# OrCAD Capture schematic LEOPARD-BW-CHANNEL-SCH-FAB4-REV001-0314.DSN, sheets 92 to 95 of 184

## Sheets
92 083_WBG - DMI & USB: size A3; title: WBG - DMI & USB
93 081_MID-PLANE CONNECTOR: size A3; title: MID-PLANE CONNECTOR
94 080_PCIE RISER: size A2; title: PCIE RISER
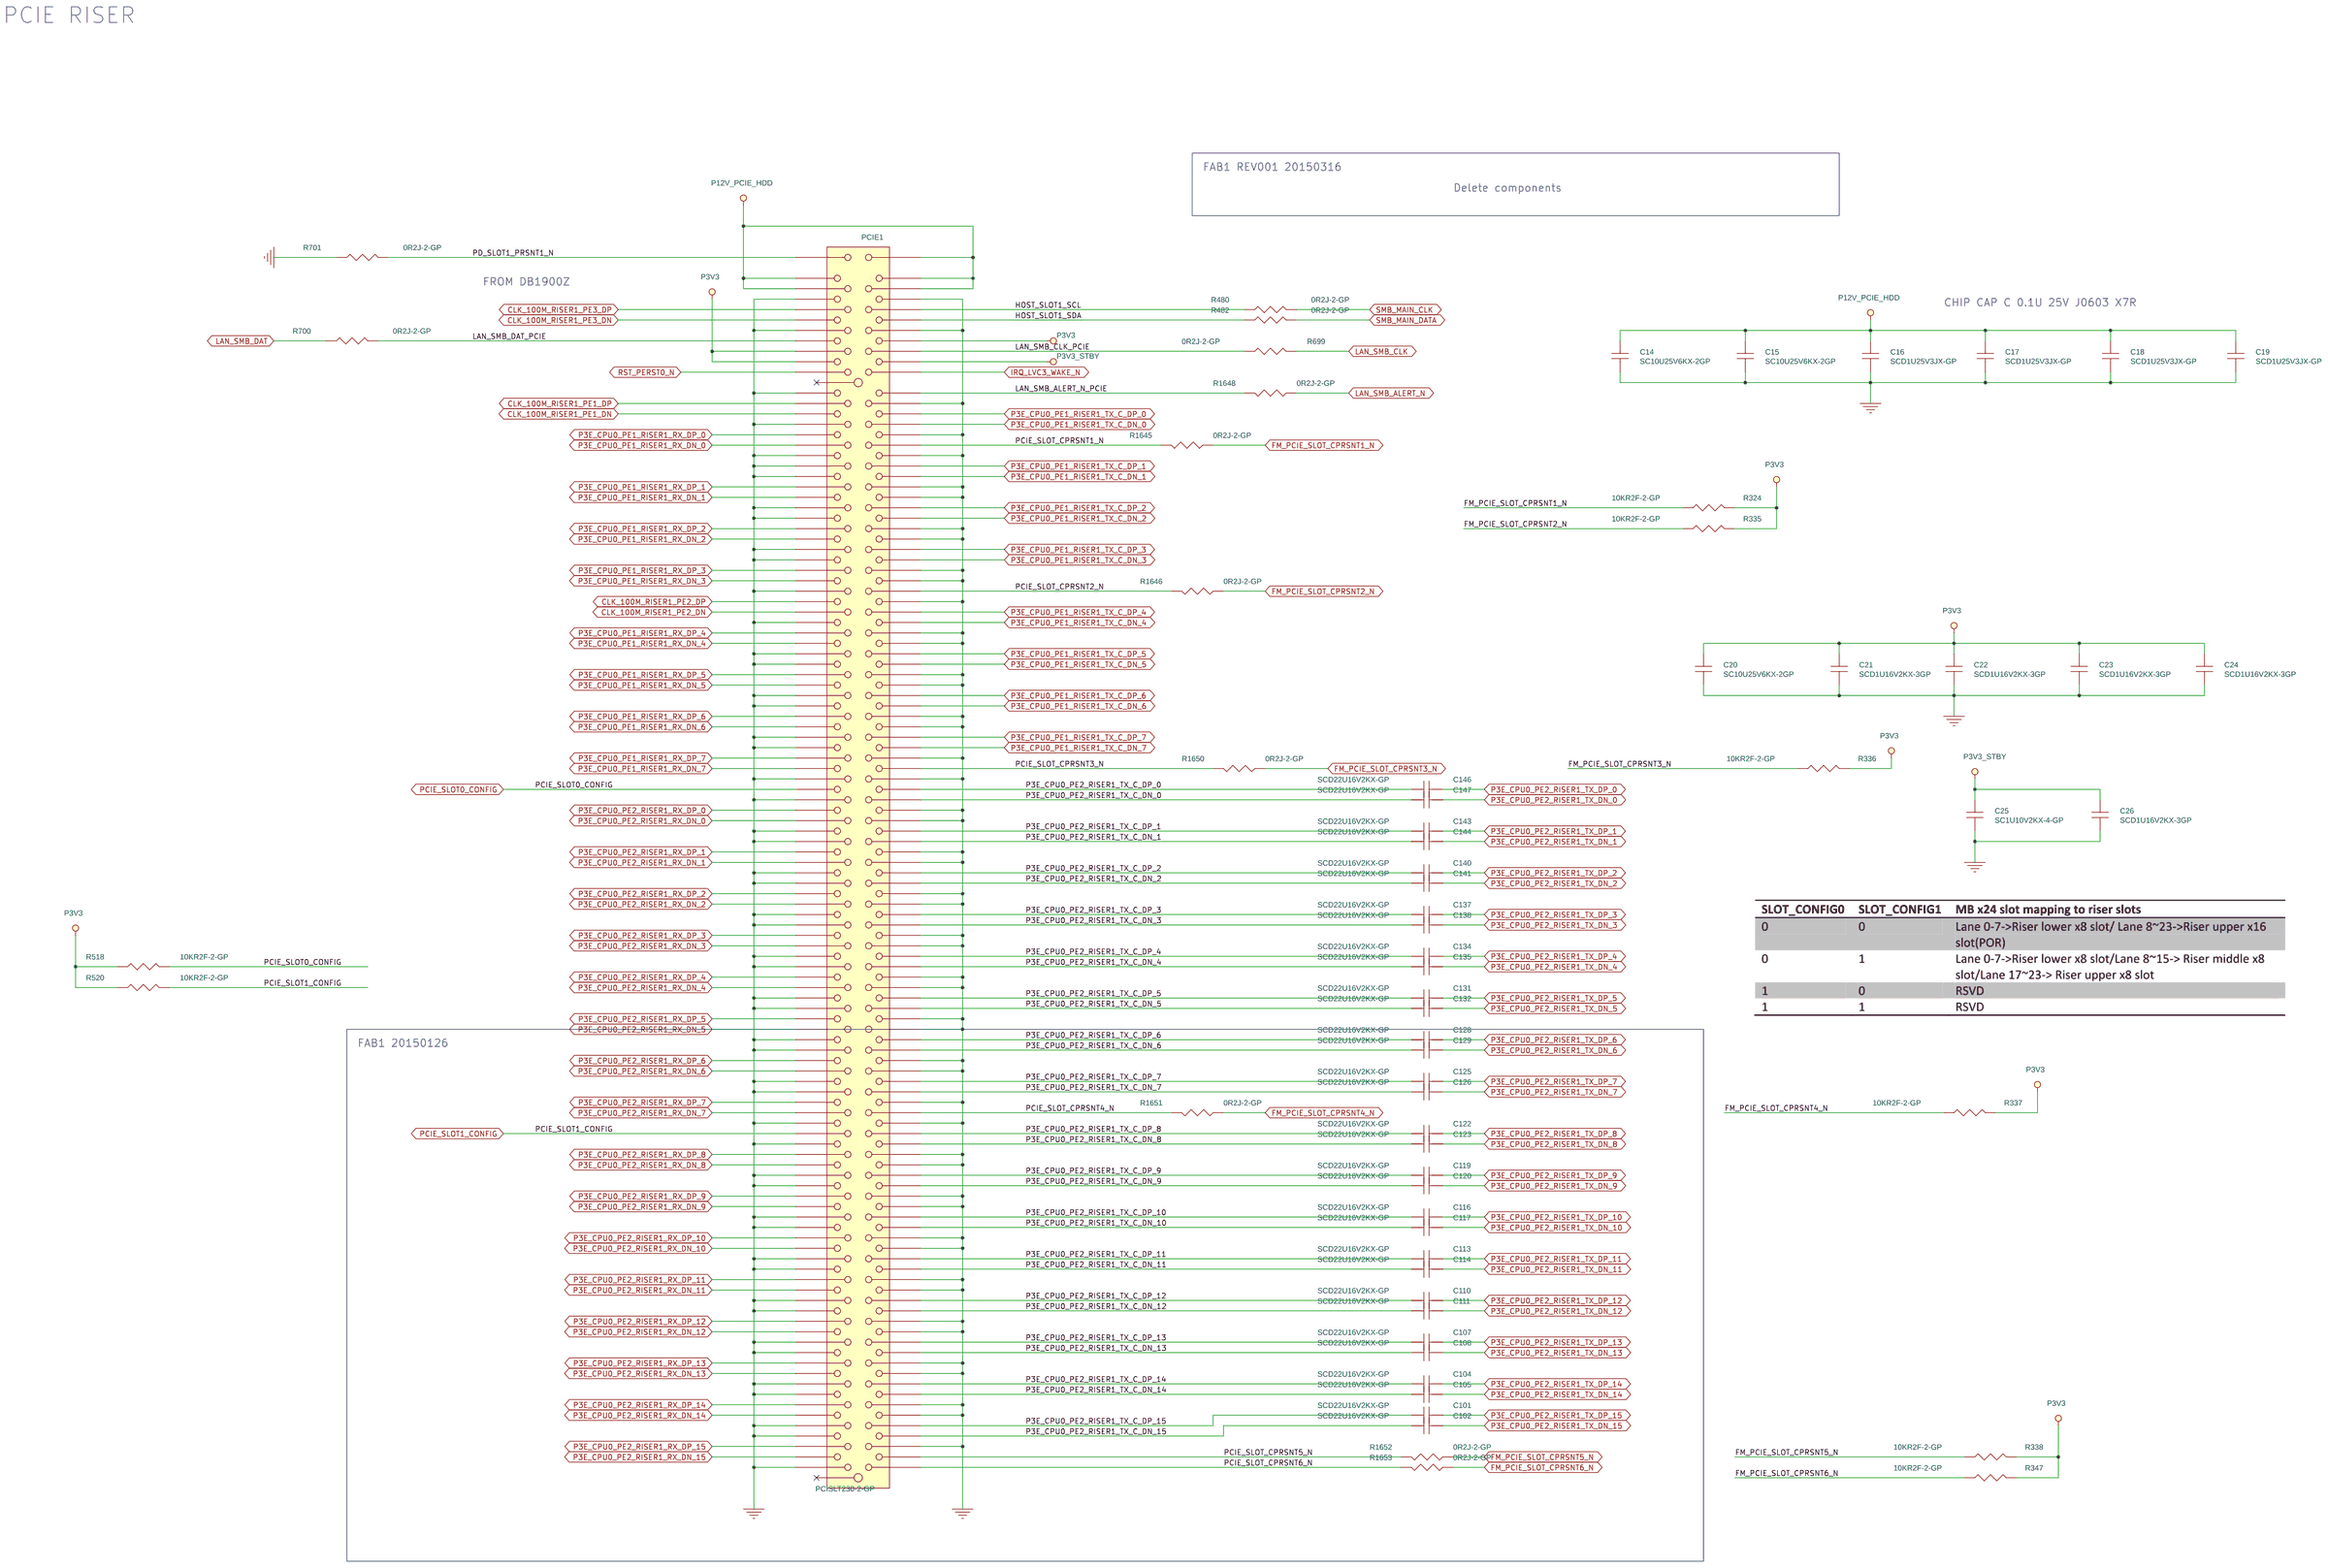
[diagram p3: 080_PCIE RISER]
95 079_MEZZ CONNECTOR: size A3; title: MEZZ CONNECTOR
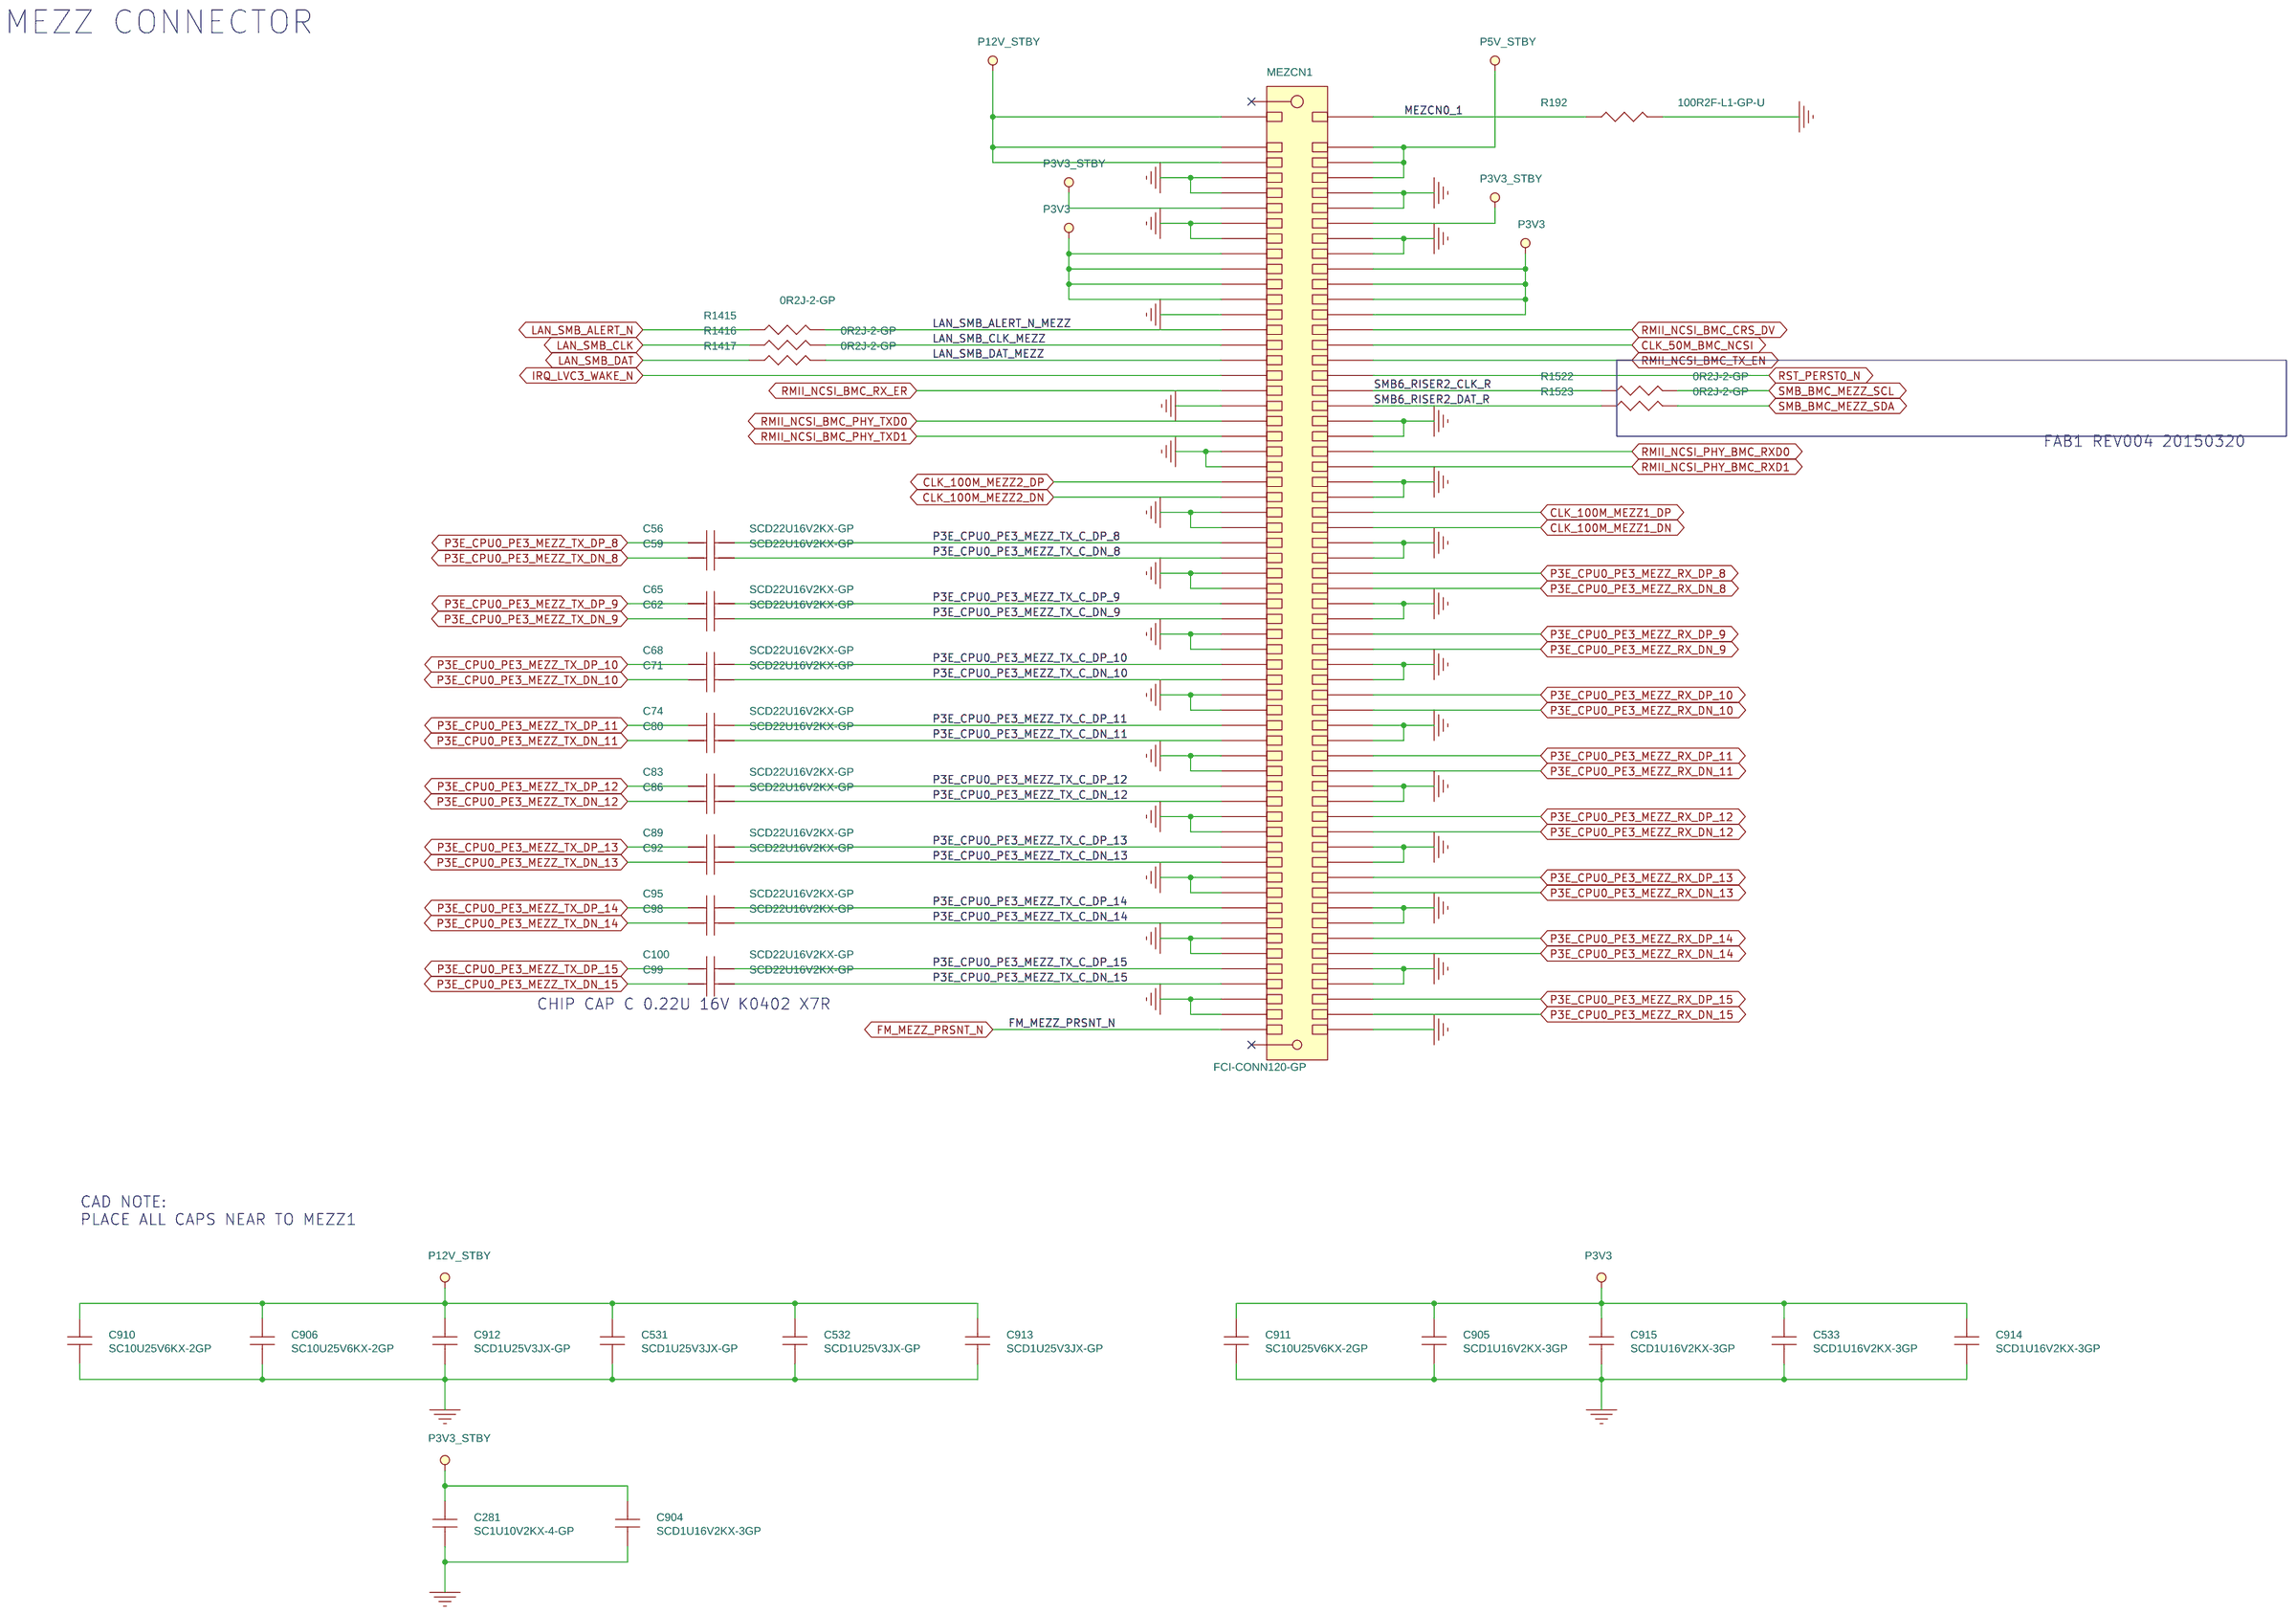
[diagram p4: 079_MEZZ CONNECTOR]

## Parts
sheet 079_MEZZ CONNECTOR
C56  SCD22U16V2KX-GP  [C402H22]
C59  SCD22U16V2KX-GP  [C402H22]
C62  SCD22U16V2KX-GP  [C402H22]
C65  SCD22U16V2KX-GP  [C402H22]
C68  SCD22U16V2KX-GP  [C402H22]
C71  SCD22U16V2KX-GP  [C402H22]
C74  SCD22U16V2KX-GP  [C402H22]
C80  SCD22U16V2KX-GP  [C402H22]
C83  SCD22U16V2KX-GP  [C402H22]
C86  SCD22U16V2KX-GP  [C402H22]
C89  SCD22U16V2KX-GP  [C402H22]
C92  SCD22U16V2KX-GP  [C402H22]
C95  SCD22U16V2KX-GP  [C402H22]
C98  SCD22U16V2KX-GP  [C402H22]
C99  SCD22U16V2KX-GP  [C402H22]
C100  SCD22U16V2KX-GP  [C402H22]
C281  SC1U10V2KX-4-GP  [C402H22]
C531  SCD1U25V3JX-GP  [C603H36]
C532  SCD1U25V3JX-GP  [C603H36]
C533  SCD1U16V2KX-3GP  [C402H22]
C904  SCD1U16V2KX-3GP  [C402H22]
C905  SCD1U16V2KX-3GP  [C402H22]
C906  SC10U25V6KX-2GP  [C1206H63]
C910  SC10U25V6KX-2GP  [C1206H63]
C911  SC10U25V6KX-2GP  [C1206H63]
C912  SCD1U25V3JX-GP  [C603H36]
C913  SCD1U25V3JX-GP  [C603H36]
C914  SCD1U16V2KX-3GP  [C402H22]
C915  SCD1U16V2KX-3GP  [C402H22]
MEZCN1  FCI-CONN120-GP  [61082-121402LF-U]
R192  100R2F-L1-GP-U  [R402H14]
R1415  0R2J-2-GP  [R402H16]
R1416  0R2J-2-GP  [R402H16]
R1417  0R2J-2-GP  [R402H16]
R1522  0R2J-2-GP  [R402H16]
R1523  0R2J-2-GP  [R402H16]
sheet 080_PCIE RISER
C14  SC10U25V6KX-2GP  [C1206H63]
C15  SC10U25V6KX-2GP  [C1206H63]
C16  SCD1U25V3JX-GP  [C603H36]
C17  SCD1U25V3JX-GP  [C603H36]
C18  SCD1U25V3JX-GP  [C603H36]
C19  SCD1U25V3JX-GP  [C603H36]
C20  SC10U25V6KX-2GP  [C1206H63]
C21  SCD1U16V2KX-3GP  [C402H22]
C22  SCD1U16V2KX-3GP  [C402H22]
C23  SCD1U16V2KX-3GP  [C402H22]
C24  SCD1U16V2KX-3GP  [C402H22]
C25  SC1U10V2KX-4-GP  [C402H22]
C26  SCD1U16V2KX-3GP  [C402H22]
C101  SCD22U16V2KX-GP  [C402H22]
C102  SCD22U16V2KX-GP  [C402H22]
C104  SCD22U16V2KX-GP  [C402H22]
C105  SCD22U16V2KX-GP  [C402H22]
C107  SCD22U16V2KX-GP  [C402H22]
C108  SCD22U16V2KX-GP  [C402H22]
C110  SCD22U16V2KX-GP  [C402H22]
C111  SCD22U16V2KX-GP  [C402H22]
C113  SCD22U16V2KX-GP  [C402H22]
C114  SCD22U16V2KX-GP  [C402H22]
C116  SCD22U16V2KX-GP  [C402H22]
C117  SCD22U16V2KX-GP  [C402H22]
C119  SCD22U16V2KX-GP  [C402H22]
C120  SCD22U16V2KX-GP  [C402H22]
C122  SCD22U16V2KX-GP  [C402H22]
C123  SCD22U16V2KX-GP  [C402H22]
C125  SCD22U16V2KX-GP  [C402H22]
C126  SCD22U16V2KX-GP  [C402H22]
C128  SCD22U16V2KX-GP  [C402H22]
C129  SCD22U16V2KX-GP  [C402H22]
C131  SCD22U16V2KX-GP  [C402H22]
C132  SCD22U16V2KX-GP  [C402H22]
C134  SCD22U16V2KX-GP  [C402H22]
C135  SCD22U16V2KX-GP  [C402H22]
C137  SCD22U16V2KX-GP  [C402H22]
C138  SCD22U16V2KX-GP  [C402H22]
C140  SCD22U16V2KX-GP  [C402H22]
C141  SCD22U16V2KX-GP  [C402H22]
C143  SCD22U16V2KX-GP  [C402H22]
C144  SCD22U16V2KX-GP  [C402H22]
C146  SCD22U16V2KX-GP  [C402H22]
C147  SCD22U16V2KX-GP  [C402H22]
PCIE1  PCISLT230-2-GP  [10063960-10010TLF]
R324  10KR2F-2-GP  [R402H16]
R335  10KR2F-2-GP  [R402H16]
R336  10KR2F-2-GP  [R402H16]
R337  10KR2F-2-GP  [R402H16]
R338  10KR2F-2-GP  [R402H16]
R347  10KR2F-2-GP  [R402H16]
R480  0R2J-2-GP  [R402H16]
R482  0R2J-2-GP  [R402H16]
R518  10KR2F-2-GP  [R402H16]
R520  10KR2F-2-GP  [R402H16]
R699  0R2J-2-GP  [R402H16]
R700  0R2J-2-GP  [R402H16]
R701  0R2J-2-GP  [R402H16]
R1645  0R2J-2-GP  [R402H16]
R1646  0R2J-2-GP  [R402H16]
R1648  0R2J-2-GP  [R402H16]
R1650  0R2J-2-GP  [R402H16]
R1651  0R2J-2-GP  [R402H16]
R1652  0R2J-2-GP  [R402H16]
R1653  0R2J-2-GP  [R402H16]
sheet 081_MID-PLANE CONNECTOR
C33  SCD1U16V2KX-3GP  [C402H22]
C173  SCD22U16V2KX-GP  [C402H22]
C174  SCD22U16V2KX-GP  [C402H22]
C176  SCD22U16V2KX-GP  [C402H22]
C177  SCD22U16V2KX-GP  [C402H22]
C179  SCD22U16V2KX-GP  [C402H22]
C180  SCD22U16V2KX-GP  [C402H22]
C182  SCD22U16V2KX-GP  [C402H22]
C183  SCD22U16V2KX-GP  [C402H22]
C185  SCD22U16V2KX-GP  [C402H22]
C186  SCD22U16V2KX-GP  [C402H22]
C188  SCD22U16V2KX-GP  [C402H22]
C189  SCD22U16V2KX-GP  [C402H22]
C191  SCD22U16V2KX-GP  [C402H22]
C192  SCD22U16V2KX-GP  [C402H22]
C194  SCD22U16V2KX-GP  [C402H22]
C195  SCD22U16V2KX-GP  [C402H22]
D13  RB521SM-30T2R-GP  [D1608-035030AKH28]
D14  RB521SM-30T2R-GP  [D1608-035030AKH28]
MIDCN1  TE-CON8-S-GP  [2-1734598-8]
MIDCN2  DM-FCI-CONN76-8R-GP-U-01  [DM-FIT76P179295UH459-01]
Q9  MMBT3904-9-GP  [SOT23CBE2D4H44]
Q18  2N7002-7F-GP  [SOT23DGS2D4H44]
R181  10KR2F-2-GP  [R402H16]
R349  10KR2F-2-GP  [R402H16]
R382  100R2F-L1-GP-U  [R402H14]
R528  0R2J-2-GP  [R402H16]
R1053  0R2J-2-GP  [R402H16]
R1217  0R2J-2-GP  [R402H16]
R1219  0R2J-2-GP  [R402H16]
R1221  6K2R2F-GP  [R402H16]
R1222  15KR2F-GP  [R402H16]
R1267  0R2J-2-GP  [R402H16]
R1384  0R2J-2-GP  [R402H16]
R1880  10KR2J-3-GP  [R402H16]
sheet 083_WBG - DMI & USB
C204  SCD1U16V2KX-3GP  [C402H22]
C205  SCD1U16V2KX-3GP  [C402H22]
C280  SCD1U16V2KX-3GP  [C402H22]
C284  SCD1U16V2KX-3GP  [C402H22]
C285  SCD1U16V2KX-3GP  [C402H22]
C286  SCD1U16V2KX-3GP  [C402H22]
C287  SCD1U16V2KX-3GP  [C402H22]
C288  SCD1U16V2KX-3GP  [C402H22]
C289  SCD1U16V2KX-3GP  [C402H22]
C290  SCD1U16V2KX-3GP  [C402H22]
C291  SCD1U16V2KX-3GP  [C402H22]
C292  SCD1U16V2KX-3GP  [C402H22]
C691  SCD1U16V2KX-3GP  [C402H22]
C693  SCD1U16V2KX-3GP  [C402H22]
C696  SCD1U16V2KX-3GP  [C402H22]
C699  SCD1U16V2KX-3GP  [C402H22]
C702  SCD1U16V2KX-3GP  [C402H22]
C703  SCD1U16V2KX-3GP  [C402H22]
C704  SCD1U16V2KX-3GP  [C402H22]
C705  SCD1U16V2KX-3GP  [C402H22]
R217  10KR2F-2-GP  [R402H16]
R282  0R2J-2-GP  [R402H16]
R321  0R2J-2-GP  [R402H16]
R397  10KR2F-2-GP  [R402H16]
R401  10KR2F-2-GP  [R402H16]
R779  8K2R2J-3-GP  [R402H16]
R888  10KR2F-2-GP  [R402H16]
R889  10KR2F-2-GP  [R402H16]
WBG1  WELLSBURG-1-GP-U  [BGA836M25H87]  (sections A,B,C,D,E,F,G,H,I,J,K)

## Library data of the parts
C56 C59 C62 C65 C68 C71 C74 C80 C83 C86 C89 C92 C95 C98-C102 C104 C105 C107 C108 C110 C111 C113 C114 C116 C117 C119 C120 C122 C123 C125 C126 C128 C129 C131 C132 C134 C135 C137 C138 C140 C141 C143 C144 C146 C147 = SCD22U16V2KX-GP: CHIP CAP C 0.22U 16V K0402 X7R; GREENDFACTOR: R2_SA;HF_SA;G_SA;; Part Number: 78.22421.2FL; Part Type: SMD-BCG4; SPEC: http://wpqssvr.wistron.com.tw:7001/wpqs/servlet/COM.qpart.Attachment?PartNumber=78.22421.2FL
C25 C281 = SC1U10V2KX-4-GP: CHIP CAP C 1U 10V K 0402 X6S; GREENDFACTOR: R2_SA;HF_SA;; Part Number: 78.10523.8FL; Part Type: SMD-BCG6; SPEC: http://wpqssvr.wistron.com.tw:7001/wpqs/servlet/COM.qpart.Attachment?PartNumber=78.10523.8FL
C16-C19 C531 C532 C912 C913 = SCD1U25V3JX-GP: CHIP CAP C 0.1U 25V J0603 X7R; GREENDFACTOR: R2_SA;HF_SA;G_SA;; Part Number: 78.10432.2BL; Part Type: SMD-BCG2; SPEC: http://wpqssvr.wistron.com.tw:7001/wpqs/servlet/COM.qpart.Attachment?PartNumber=78.10432.2BL
C21-C24 C26 C533 C904 C905 C914 C915 = SCD1U16V2KX-3GP: CHIP CAP C 0.1U 16V K0402 X7R; CATEGORIES: CAP_1.xV; GREENDFACTOR: R2_SA;HF_SA;G_SA;; MAIN_SOURCE: M; Part Number: 78.10421.2FL; Part Type: SMD-BCG; SPEC: http://wpqssvr.wistron.com.tw:7001/wpqs/servlet/COM.qpart.Attachment?PartNumber=78.10421.2FL
C14 C15 C20 C906 C910 C911 = SC10U25V6KX-2GP: CHIP CAP C 10U 25V K1206 X6S; GREENDFACTOR: R2_SA;HF_SA;; Part Number: 78.10622.82L; Part Type: SMD-BCG; SPEC: http://wpqssvr.wistron.com.tw:7001/wpqs/servlet/COM.qpart.Attachment?PartNumber=78.10622.82L
MEZCN1 = FCI-CONN120-GP: CONN CTR SMD 120P 61082-121402LF; Category: MEZZ CONN; GREENDFACTOR: R2_C;; Part Number: 20.F1354.120; Part Type: CONN-G6; SPEC: http://wpqssvr.wistron.com.tw:7001/wpqs/servlet/COM.qpart.Attachment?PartNumber=20.F1354.120
R192 = 100R2F-L1-GP-U: CHIP RES 100 F 1/16W 0402; GREENDFACTOR: R2_SA;HF_SA;G_SA;; Part Number: 64.10005.6DL; Part Type: SMD-RG; SPEC: http://wpqssvr.wistron.com.tw:7001/wpqs/servlet/COM.qpart.Attachment?PartNumber=64.10005.6DL
R1415 = 0R2J-2-GP: CHIP RES 0 J 1/16W 0402; Belong: POP; Category: MEZZ CONN; Part Number: 63.R0034.1DL; Part Type: SMD-RG; Status: POP
R1416 R1417 R1522 R1523 = 0R2J-2-GP: CHIP RES 0 J 1/16W 0402; Belong: POP; Category: MEZZ CONN; GREENDFACTOR: R2_SA;HF_SA;G_SA;; Part Number: 63.R0034.1DL; Part Type: SMD-RG; SPEC: http://wpqssvr.wistron.com.tw:7001/wpqs/servlet/COM.qpart.Attachment?PartNumber=63.R0034.1DL
PCIE1 = PCISLT230-2-GP: CONN EDGE 230P ST 10063960-10010TLF; GREENDFACTOR: R2_SA;; Part Number: 20.50552.230; Part Type: CONN-G7; SPEC: http://wpqssvr.wistron.com.tw:7001/wpqs/servlet/COM.qpart.Attachment?PartNumber=20.50552.230
R217 R324 R335-R338 R347 R518 R520 = 10KR2F-2-GP: CHIP RES 10K F 1/16W 0402; Category: PCH; DESCRIPTIO: CHIP RES 10K F 1/16W 0402; GREENDFACTOR: R2_SA;HF_SA;G_SA;; Package Type: SMD-RG; Part Number: 64.10025.6DL; Part Type: SMD-RG; SPEC: http://wpqssvr.wistron.com.tw:7001/wpqs/servlet/COM.qpart.Attachment?PartNumber=64.10025.6DL; VENDORPARTNUMBER: RM04FTN1002 / RTT021002FTH / RR0510S-103-FN / RC0402FR-0710KL/WR04X1002FTL
R480 R482 R699-R701 = 0R2J-2-GP: CHIP RES 0 J 1/16W 0402; GREENDFACTOR: R2_SA;HF_SA;G_SA;; Package Type: SMD-RG; Part Number: 63.R0034.1DL; SPEC: http://wpqssvr.wistron.com.tw:7001/wpqs/servlet/COM.qpart.Attachment?PartNumber=63.R0034.1DL
R1645 R1646 R1648 R1650-R1653 = 0R2J-2-GP: CHIP RES 0 J 1/16W 0402; Category: BMC; DESCRIPTIO: CHIP RES 0 J 1/16W 0402; GREENDFACTOR: R2_SA;HF_SA;G_SA;; Package Type: SMD-RG; Part Number: 63.R0034.1DL; Part Type: SMD-RG; SPEC: http://wpqssvr.wistron.com.tw:7001/wpqs/servlet/COM.qpart.Attachment?PartNumber=63.R0034.1DL; VENDORPARTNUMBER: RM04JTN0/RTT02000JTH/RR0510X-000-XN/RC0402JR-070RL/WR04X000 PTL
C33 = SCD1U16V2KX-3GP: CHIP CAP C 0.1U 16V K0402 X7R; CATEGORIES: CAP_1.xV; GREENDFACTOR: R2_SA;HF_SA;G_SA;; MAIN_SOURCE: M; POP?: NOPOP; Part Number: 78.10421.2FL; Part Type: SMD-BCG; SPEC: http://wpqssvr.wistron.com.tw:7001/wpqs/servlet/COM.qpart.Attachment?PartNumber=78.10421.2FL
C173 C174 C176 C177 C179 C180 C182 C183 C185 C186 C188 C189 C191 C192 C194 C195 = SCD22U16V2KX-GP: CHIP CAP C 0.22U 16V K0402 X7R; GREENDFACTOR: R2_SA;HF_SA;G_SA;; POP?: NOPOP; Part Number: 78.22421.2FL; Part Type: SMD-BCG4; SPEC: http://wpqssvr.wistron.com.tw:7001/wpqs/servlet/COM.qpart.Attachment?PartNumber=78.22421.2FL
D13 D14 = RB521S-30TE61-GP: DIODE S.B. RB521SM-30T2R EMD2; Category: internal conn; DESCRIPTIO: DIODE RB521S-30TE61 SMT2 LF; GREENDFACTOR: R2_SA;HF_SA;; POP?: NOPOP; Package Type: DISCRET-G6; Part Number: 83.1R003.P8F; Part Type: DISCRET-G6; SPEC: http://wpqssvr.wistron.com.tw:7001/wpqs/servlet/COM.qpart.Attachment?PartNumber=83.1R003.P8F; VENDORPARTNUMBER: RB521SM-30T2R
MIDCN1 = TE-CON8-S-GP: HEAD ML 1R8P 2-1734598-8, PA9T; GREENDFACTOR: R2_C;; POP?: NOPOP; Part Number: 021.60329.0108; Part Type: CONN-G6; SPEC: http://wpqssvr.wistron.com.tw:7001/wpqs/servlet/COM.qpart.Attachment?PartNumber=021.60329.0108
MIDCN2 = DM-FCI-CONN76-8R-GP-U-01: CONN CTR 48S+28G 10124755-111LF PRESSFIT; GREENDFACTOR: R2_C;; POP?: NOPOP; Part Number: ZZ.82092.07601; Part Type: CONN-G4; SPEC: http://wpqssvr.wistron.com.tw:7001/wpqs/servlet/COM.qpart.Attachment?PartNumber=ZZ.82092.07601
Q9 = MMBT3904-9-GP: XTOR MMBT3904 NPN SOT-23; GREENDFACTOR: R2_SA;; POP?: NOPOP; Part Number: 084.03904.0B11; Part Type: DISCRET-G9; SPEC: http://wpqssvr.wistron.com.tw:7001/wpqs/servlet/COM.qpart.Attachment?PartNumber=084.03904.0B11
Q18 = 2N7002-7F-GP: FET MOS 2N7002-7-F NC SOT-23; GREENDFACTOR: R2_SA;HF_SA;G_SA;; POP?: NOPOP; Part Number: 84.27002.N31; Part Type: DISCRET-G; SPEC: http://wpqssvr.wistron.com.tw:7001/wpqs/servlet/COM.qpart.Attachment?PartNumber=84.27002.N31
R181 = 10KR2F-2-GP: CHIP RES 10K F 1/16W 0402; GREENDFACTOR: R2_SA;HF_SA;G_SA;; Level: SMD; POP?: NOPOP; Package Type: SMD-RG; Part Number: 64.10025.6DL; Part Type: SMD-RG; SPEC: http://wpqssvr.wistron.com.tw:7001/wpqs/servlet/COM.qpart.Attachment?PartNumber=64.10025.6DL
R349 = 10KR2F-2-GP: CHIP RES 10K F 1/16W 0402; Category: PCH; DESCRIPTIO: CHIP RES 10K F 1/16W 0402; GREENDFACTOR: R2_SA;HF_SA;G_SA;; POP?: NOPOP; Package Type: SMD-RG; Part Number: 64.10025.6DL; Part Type: SMD-RG; SPEC: http://wpqssvr.wistron.com.tw:7001/wpqs/servlet/COM.qpart.Attachment?PartNumber=64.10025.6DL; VENDORPARTNUMBER: RM04FTN1002 / RTT021002FTH / RR0510S-103-FN / RC0402FR-0710KL/WR04X1002FTL
R382 = 100R2F-L1-GP-U: CHIP RES 100 F 1/16W 0402; Category: CPU SIDE BAND; POP?: NOPOP; Part Number: 64.10005.6DL; Part Type: SMD-RG
R528 R1053 R1384 = 0R2J-2-GP: CHIP RES 0 J 1/16W 0402; Belong: POP; Category: PWRI/O CONN; GREENDFACTOR: R2_SA;R_SA;HF_SA;G_SA;; POP?: NOPOP; Package Type: SMD-RG; Part Number: 63.R0034.1DL; Part Type: SMD-RG; SPEC: http://wpqssvr.wistron.com.tw:7001/wpqs/servlet/COM.qpart.Attachment?PartNumber=63.R0034.1DL
R1217 R1219 R1267 = 0R2J-2-GP: CHIP RES 0 J 1/16W 0402; GREENDFACTOR: R2_SA;HF_SA;G_SA;; POP?: NOPOP; Package Type: SMD-RG; Part Number: 63.R0034.1DL; SPEC: http://wpqssvr.wistron.com.tw:7001/wpqs/servlet/COM.qpart.Attachment?PartNumber=63.R0034.1DL
R1221 = 6K2R2F-GP: CHIP RES 6.2K F 1/16W 0402; GREENDFACTOR: R2_SA;HF_SA;G_SA;; Part Number: 64.62015.6DL; Part Type: RCL_GP; SPEC: http://wpqssvr.wistron.com.tw:7001/wpqs/servlet/COM.qpart.Attachment?PartNumber=64.62015.6DL
R1222 = 15KR2F-GP: CHIP RES 15K F 1/16W 0402; GREENDFACTOR: R2_SA;HF_SA;G_SA;; Package Type: RCL_GP; Part Number: 64.15025.6DL; SPEC: http://wpqssvr.wistron.com.tw:7001/wpqs/servlet/COM.qpart.Attachment?PartNumber=64.15025.6DL
R1880 = 10KR2J-3-GP: CHIP RES 10K J 1/16W 0402; Category: PWRI/O CONN; GREENDFACTOR: R2_SA;HF_SA;G_SA;; Module: Internal Connector; POP?: NOPOP; Package Type: SMD-RG; Part Number: 63.10334.1DL; SPEC: http://wpqssvr.wistron.com.tw:7001/wpqs/servlet/COM.qpart.Attachment?PartNumber=63.10334.1DL
C204 C205 C291 C292 = SCD1U16V2KX-3GP: CHIP CAP C 0.1U 16V K0402 X7R; Category: Powervill; GREENDFACTOR: R_SA;HF_SA;G_SA;; Part Number: 78.10421.2FL; Quotation: 9_7; Type: SMD
C280 C284-C290 = SCD1U16V2KX-3GP: CHIP CAP C 0.1U 16V K0402 X7R; Category: Powervill; GREENDFACTOR: R_SA;HF_SA;G_SA;; POP?: NOPOP; Part Number: 78.10421.2FL; Quotation: 9_7; Type: SMD
C691 C693 C696 C699 C702-C705 = SCD1U16V2KX-3GP: CHIP CAP C 0.1U 16V K0402 X7R; Category: PCH; GREENDFACTOR: R_SA;HF_SA;G_SA;; Part Number: 78.10421.2FL; Quotation: 13_8; Type: SMD
R282 R321 = 0R2J-2-GP: CHIP RES 0 J 1/16W 0402; Category: PCH; DESCRIPTIO: CHIP RES 0 J 1/16W 0402; GREENDFACTOR: R2_SA;HF_SA;G_SA;; POP?: NOPOP; Package Type: SMD-RG; Part Number: 63.R0034.1DL; Part Type: SMD-RG; SPEC: http://wpqssvr.wistron.com.tw:7001/wpqs/servlet/COM.qpart.Attachment?PartNumber=63.R0034.1DL; VENDORPARTNUMBER: RM04JTN0/RTT02000JTH/RR0510X-000-XN/RC0402JR-070RL/WR04X000 PTL
R397 R401 = 10KR2F-2-GP: CHIP RES 10K F 1/16W 0402; GREENDFACTOR: R2_SA;HF_SA;G_SA;; Package Type: SMD-RG; Part Number: 64.10025.6DL; SPEC: http://wpqssvr.wistron.com.tw:7001/wpqs/servlet/COM.qpart.Attachment?PartNumber=64.10025.6DL
R779 = 8K2R2J-3-GP: CHIP RES 8.2K J 1/16W 0402; Category: BMC; DESCRIPTIO: CHIP RES 8.2K J 1/16W 0402; GREENDFACTOR: R2_SA;HF_SA;G_SA;; Package Type: SMD-RG; Part Number: 63.82234.1DL; Part Type: SMD-RG; SPEC: http://wpqssvr.wistron.com.tw:7001/wpqs/servlet/COM.qpart.Attachment?PartNumber=63.82234.1DL; VENDORPARTNUMBER: RM04JTN822 / RTT02822JTH / RR0510S-822-JN / RC0402JR-078K2L/WR04X822JTL
R888 R889 = 10KR2J-3-GP: CHIP RES 10K F 1/16W 0402; Category: PCH; DESCRIPTIO: CHIP RES 10K J 1/16W 0402; GREENDFACTOR: R2_SA;HF_SA;G_SA;; Package Type: SMD-RG; Part Number: 64.10025.6DL; Part Type: SMD-RG; SPEC: http://wpqssvr.wistron.com.tw:7001/wpqs/servlet/COM.qpart.Attachment?PartNumber=64.10025.6DL; Type: SMD; VENDORPARTNUMBER: RM04FTN1002 / RTT021002FTH / RR0510S-103-FN / RC0402FR-0710KL/WR04X1002FTL; Vendor PN: RR0510S-103-JN/RTT02103JTH/RM04JTN103/WR04X103JTL/RC0402JR-0710KL
WBG1 = WELLSBURG-1-GP-U: IC PCH WELLSBURG FCBGA 836P(SERVER); GREENDFACTOR: R2_C;; POP?: 071.82029.0B0U; Package Type: ASIC2-G4; Part Number: 71.WSBUG.00U; SPEC: http://wpqssvr.wistron.com.tw:7001/wpqs/servlet/COM.qpart.Attachment?PartNumber=71.WSBUG.00U

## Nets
GND: C14.2 C15.2 C16.2 C17.2 C18.2 C19.2 C20.2 C21.2 C22.2 C23.2 C24.2 C25.2 C26.2 C33.2 C281.2 C531.2 C532.2 C533.2 C904.2 C905.2 C906.2 C910.2 C911.2 C912.2 C913.2 C914.2 C915.2 MEZCN1.5 MEZCN1.6 MEZCN1.8 MEZCN1.9 MEZCN1.20 MEZCN1.21 MEZCN1.24 MEZCN1.25 MEZCN1.28 MEZCN1.29 MEZCN1.32 MEZCN1.33 MEZCN1.36 MEZCN1.37 MEZCN1.40 MEZCN1.41 MEZCN1.44 MEZCN1.45 MEZCN1.48 MEZCN1.49 MEZCN1.52 MEZCN1.53 MEZCN1.56 MEZCN1.57 MEZCN1.60 MEZCN1.64 MEZCN1.65 MEZCN1.67 MEZCN1.68 MEZCN1.73 MEZCN1.79 MEZCN1.82 MEZCN1.83 MEZCN1.86 MEZCN1.87 MEZCN1.90 MEZCN1.91 MEZCN1.94 MEZCN1.95 MEZCN1.98 MEZCN1.99 MEZCN1.102 MEZCN1.103 MEZCN1.106 MEZCN1.107 MEZCN1.110 MEZCN1.111 MEZCN1.114 MEZCN1.115 MEZCN1.118 MEZCN1.119 MIDCN1.8 MIDCN2.A2(GND1) MIDCN2.A8(GND2) MIDCN2.C1(GND3) MIDCN2.C3(GND4) MIDCN2.C5(GND5) MIDCN2.C7(GND6) MIDCN2.D2(GND7) MIDCN2.D6(GND8) MIDCN2.D8(GND9) MIDCN2.F1(GND10) MIDCN2.F3(GND11) MIDCN2.F7(GND12) MIDCN2.G2(GND13) MIDCN2.G4(GND14) MIDCN2.G6(GND15) MIDCN2.G8(GND16) MIDCN2.I1(GND17) MIDCN2.I7(GND18) MIDCN2.J2 MIDCN2.J4 MIDCN2.J6 MIDCN2.J8 PCIE1.A4 PCIE1.A7 PCIE1.A12 PCIE1.A15 PCIE1.A18 PCIE1.A19 PCIE1.A20 PCIE1.A23 PCIE1.A24 PCIE1.A27 PCIE1.A28 PCIE1.A31 PCIE1.A34 PCIE1.A37 PCIE1.A38 PCIE1.A41 PCIE1.A42 PCIE1.A45 PCIE1.A46 PCIE1.A49 PCIE1.A51 PCIE1.A54 PCIE1.A55 PCIE1.A58 PCIE1.A59 PCIE1.A62 PCIE1.A63 PCIE1.A66 PCIE1.A67 PCIE1.A70 PCIE1.A71 PCIE1.A74 PCIE1.A75 PCIE1.A78 PCIE1.A79 PCIE1.A82 PCIE1.A84 PCIE1.A87 PCIE1.A88 PCIE1.A91 PCIE1.A92 PCIE1.A95 PCIE1.A96 PCIE1.A99 PCIE1.A100 PCIE1.A103 PCIE1.A104 PCIE1.A107 PCIE1.A108 PCIE1.A111 PCIE1.A112 PCIE1.A115 PCIE1.B4 PCIE1.B7 PCIE1.B13 PCIE1.B16 PCIE1.B18 PCIE1.B21 PCIE1.B22 PCIE1.B25 PCIE1.B26 PCIE1.B29 PCIE1.B30 PCIE1.B32 PCIE1.B35 PCIE1.B36 PCIE1.B39 PCIE1.B40 PCIE1.B43 PCIE1.B44 PCIE1.B47 PCIE1.B49 PCIE1.B52 PCIE1.B53 PCIE1.B56 PCIE1.B57 PCIE1.B60 PCIE1.B61 PCIE1.B64 PCIE1.B65 PCIE1.B68 PCIE1.B69 PCIE1.B72 PCIE1.B73 PCIE1.B76 PCIE1.B77 PCIE1.B80 PCIE1.B82 PCIE1.B85 PCIE1.B86 PCIE1.B89 PCIE1.B90 PCIE1.B93 PCIE1.B94 PCIE1.B97 PCIE1.B98 PCIE1.B101 PCIE1.B102 PCIE1.B105 PCIE1.B106 PCIE1.B109 PCIE1.B110 PCIE1.B113 Q9.E Q18.S R181.2 R192.2 R382.2 R397.2 R401.2 R701.2 R888.2 R889.2 R1221.2 ; also on sheet 1 2 3 4 5 6 7 8 9 10 11 12 13 14 15 16 17 18 19 20 21 22 23 24 25 26 27 28 29 30 31 32 33 34 35 36 37 38 39 44 46 47 49 50 51 52 53 54 55 56 57 58 59 60 61 62 63 64 65 66 69 70 71 73 74 75 76 78 79 80 81 82 83 84 86 87 88 89 90 91 96 97 98 99 100 101 102 103 104 105 106 107 108 109 110 111 112 113 114 115 116 117 118 119 128 129 138 139 159 160 161 166 168 169 170 171 172 173 174 175 176 177 180 181 182 183 184
P3V3: C20.1 C21.1 C22.1 C23.1 C24.1 C533.1 C905.1 C911.1 C914.1 C915.1 MEZCN1.10 MEZCN1.11 MEZCN1.12 MEZCN1.13 MEZCN1.69 MEZCN1.70 MEZCN1.71 MEZCN1.72 PCIE1.A9 PCIE1.A10 PCIE1.B8 R324.1 R335.1 R336.1 R337.1 R338.1 R347.1 R518.1 R520.1 ; also on sheet 1 3 8 45 46 48 49 52 54 58 65 74 76 78 83 84 87 90 91 96 100 101 102 161 166 168 173 174 177 180 181 182 183
P3V3_STBY: C25.1 C26.1 C33.1 C281.1 C904.1 MEZCN1.7 MEZCN1.66 MIDCN1.1 PCIE1.B10 R217.1 R779.1 R1880.1 ; also on sheet 2 3 5 6 8 9 10 11 12 15 16 17 20 21 22 25 26 27 30 31 33 34 35 37 38 39 45 47 49 50 51 52 54 55 59 60 61 62 63 64 65 66 69 70 71 72 73 74 76 79 83 84 87 88 89 90 91 96 97 98 99 159 161 166 168 173 174 176 177 179 180 182 183 184
P5V_STBY: MEZCN1.2 MEZCN1.3 MEZCN1.4 ; also on sheet 4 5 6 8 14 15 19 20 24 25 29 30 33 34 37 38 59 61 65 69 76
P12V_MAIN: R349.2 R1222.1 ; also on sheet 53 60
P12V_PCIE_HDD: C14.1 C15.1 C16.1 C17.1 C18.1 C19.1 PCIE1.A2 PCIE1.A3 PCIE1.B1 PCIE1.B2 PCIE1.B3 ; also on sheet 59 76 80 82
P12V_STBY: C531.1 C532.1 C906.1 C910.1 C912.1 C913.1 MEZCN1.61 MEZCN1.62 MEZCN1.63 ; also on sheet 2 3 4 7 9 10 11 12 13 17 18 22 23 27 28 32 36 59 60 75 104 105 106 107 108 109 110 111 112 113 114 115 116 117 118 119
CLK_50M_BMC_NCSI: MEZCN1.15 ; also on sheet 55
CLK_96M_PCH_DN: R397.1 WBG1.AM35(CLKIN_DOT96_N)
CLK_96M_PCH_DP: R401.1 WBG1.AM36(CLKIN_DOT96_P)
CLK_100M_MEZZ1_DN: MEZCN1.27 ; also on sheet 57
CLK_100M_MEZZ1_DP: MEZCN1.26 ; also on sheet 57
CLK_100M_MEZZ2_DN: MEZCN1.85 ; also on sheet 57
CLK_100M_MEZZ2_DP: MEZCN1.84 ; also on sheet 57
CLK_100M_PCH_BMC_DN: R282.2 ; also on sheet 74
CLK_100M_PCH_BMC_DP: R321.2 ; also on sheet 74
CLK_100M_PCH_BMC_R_DN: R282.1 WBG1.BE2(CLKOUT_DMI_N0)
CLK_100M_PCH_BMC_R_DP: R321.1 WBG1.BD4(CLKOUT_DMI_P0)
CLK_100M_RISER1_PE1_DN: PCIE1.A14 ; also on sheet 57
CLK_100M_RISER1_PE1_DP: PCIE1.A13 ; also on sheet 57
CLK_100M_RISER1_PE2_DN: PCIE1.A33 ; also on sheet 57
CLK_100M_RISER1_PE2_DP: PCIE1.A32 ; also on sheet 57
CLK_100M_RISER1_PE3_DN: PCIE1.A6 ; also on sheet 57
CLK_100M_RISER1_PE3_DP: PCIE1.A5 ; also on sheet 57
CLK_100M_RISER2_PE1_DN: MIDCN2.I4(PCIE_CLK_100M_DN) ; also on sheet 57
CLK_100M_RISER2_PE1_DP: MIDCN2.H4(PCIE_CLK_100M_DP) ; also on sheet 57
COM3_RXD: MIDCN2.H3(COM_RX) ; also on sheet 70
COM3_TXD: MIDCN2.G3(COM_TX) ; also on sheet 70
CPU_CACHE_FLUSH_TRIGGER_N: R217.2 WBG1.G44(OC4#/GPIO43) ; also on sheet 48
DMI_CPU0_PCH_RX_C_DN_0: C705.2 ; also on sheet 133
DMI_CPU0_PCH_RX_C_DN_1: C699.2 ; also on sheet 133
DMI_CPU0_PCH_RX_C_DN_2: C696.2 ; also on sheet 133
DMI_CPU0_PCH_RX_C_DN_3: C693.2 ; also on sheet 133
DMI_CPU0_PCH_RX_C_DP_0: C704.2 ; also on sheet 133
DMI_CPU0_PCH_RX_C_DP_1: C703.2 ; also on sheet 133
DMI_CPU0_PCH_RX_C_DP_2: C702.2 ; also on sheet 133
DMI_CPU0_PCH_RX_C_DP_3: C691.2 ; also on sheet 133
DMI_CPU0_PCH_RX_DN_0: C705.1 WBG1.M2(DMI_TXN0)
DMI_CPU0_PCH_RX_DN_1: C699.1 WBG1.K2(DMI_TXN1)
DMI_CPU0_PCH_RX_DN_2: C696.1 WBG1.H2(DMI_TXN2)
DMI_CPU0_PCH_RX_DN_3: C693.1 WBG1.E2(DMI_TXN3)
DMI_CPU0_PCH_RX_DP_0: C704.1 WBG1.M4(DMI_TXP0)
DMI_CPU0_PCH_RX_DP_1: C703.1 WBG1.K4(DMI_TXP1)
DMI_CPU0_PCH_RX_DP_2: C702.1 WBG1.H4(DMI_TXP2)
DMI_CPU0_PCH_RX_DP_3: C691.1 WBG1.F4(DMI_TXP3)
DMI_CPU0_PCH_TX_C_DN_0: WBG1.T12(DMI_RXN0) ; also on sheet 133
DMI_CPU0_PCH_TX_C_DN_1: WBG1.T7(DMI_RXN1) ; also on sheet 133
DMI_CPU0_PCH_TX_C_DN_2: WBG1.N7(DMI_RXN2) ; also on sheet 133
DMI_CPU0_PCH_TX_C_DN_3: WBG1.J6(DMI_RXN3) ; also on sheet 133
DMI_CPU0_PCH_TX_C_DP_0: WBG1.T14(DMI_RXP0) ; also on sheet 133
DMI_CPU0_PCH_TX_C_DP_1: WBG1.T9(DMI_RXP1) ; also on sheet 133
DMI_CPU0_PCH_TX_C_DP_2: WBG1.N6(DMI_RXP2) ; also on sheet 133
DMI_CPU0_PCH_TX_C_DP_3: WBG1.L6(DMI_RXP3) ; also on sheet 133
FAN0_PWM: MIDCN2.F4(FAN_PWM0) ; also on sheet 66
FAN0_TACH: MIDCN2.D4(FAN_TACH0) ; also on sheet 66
FAN0_TACH0A: MIDCN2.C4(FAN_TACH1) ; also on sheet 66
FAN1_TACH: MIDCN2.B4(FAN_TACH2) ; also on sheet 66
FAN1_TACH1A: MIDCN2.A4(FAN_TACH3) ; also on sheet 66
FM_MEZZ_PRSNT_N: MEZCN1.120 ; also on sheet 90
FM_PCIE_SLOT_CPRSNT1_N: R324.2 R1645.1 ; also on sheet 166
FM_PCIE_SLOT_CPRSNT2_N: R335.2 R1646.1 ; also on sheet 91
FM_PCIE_SLOT_CPRSNT3_N: R336.2 R1650.1 ; also on sheet 88
FM_PCIE_SLOT_CPRSNT4_N: R337.2 R1651.1 ; also on sheet 88
FM_PCIE_SLOT_CPRSNT5_N: R338.2 R1652.1 ; also on sheet 88
FM_PCIE_SLOT_CPRSNT6_N: R347.2 R1653.1 ; also on sheet 88
FM_PS_EN: Q18.G R181.1 ; also on sheet 51 59
HOST_SLOT1_SCL: PCIE1.B5 R480.2
HOST_SLOT1_SDA: PCIE1.B6 R482.2
IRQ_LVC3_WAKE_N: MEZCN1.77 PCIE1.B11 ; also on sheet 64 74 81 83 88 168
IRQ_MID_PMBUS_ALERT_N: MIDCN1.5 MIDCN2.A6(PMBUS_ALERT#) ; also on sheet 54
LAN_SMB_ALERT_N: R1415.2 R1648.1 ; also on sheet 64 74
LAN_SMB_ALERT_N_MEZZ: MEZCN1.74 R1415.1
LAN_SMB_ALERT_N_PCIE: PCIE1.B12 R1648.2
LAN_SMB_CLK: R699.2 R1416.1 ; also on sheet 64 74 77
LAN_SMB_CLK_MEZZ: MEZCN1.75 R1416.2
LAN_SMB_CLK_PCIE: PCIE1.B9 R699.1
LAN_SMB_DAT: R700.2 R1417.1 ; also on sheet 64 74 77
LAN_SMB_DAT_MEZZ: MEZCN1.76 R1417.2
LAN_SMB_DAT_PCIE: PCIE1.A8 R700.1
MATED_IN_N: D13.A(ANODE) R349.1 R382.1 R1384.1
MATED_IN_N_D: D13.K(CATHODE) D14.A(ANODE)
MATED_IN_N_Q: D14.K(CATHODE) Q9.B
MATED_IN_N_R: MIDCN1.4 MIDCN2.E4(MATED_IN#) R1384.2
MB0_HS_ENABLE: Q9.C R1221.1 R1222.2 ; also on sheet 60
MB_ON_N: MIDCN2.I3(MB_ON#) R528.1
MB_ON_N_R: Q18.D R528.2 R1880.2
MB_SLOT_ID0: R1267.2 ; also on sheet 177
MB_SLOT_ID0_R: MIDCN2.F5(MB_SLOT_ID0) R1267.1
MB_SLOT_ID1: R1217.2 ; also on sheet 177
MB_SLOT_ID1_R: MIDCN2.G5(MB_SLOT_ID1) R1217.1
MB_SLOT_ID2: R1219.2 ; also on sheet 177
MB_SLOT_ID2_R: MIDCN2.H5(MB_SLOT_ID2) R1219.1
MEZCN0_1: MEZCN1.1 R192.1
MNG_RX_DN: MIDCN2.E5(MNG_RX_DN) ; also on sheet 63
MNG_RX_DP: MIDCN2.D5(MNG_RX_DP) ; also on sheet 63
MNG_TX_DN: MIDCN2.B5(MNG_TX_DN) ; also on sheet 63
MNG_TX_DP: MIDCN2.A5(MNG_TX_DP) ; also on sheet 63
NOA_0_FM_USB_OC_0_N: WBG1.J43(OC0#/GPIO59) ; also on sheet 48
NOA_1_FM_USB_OC_1_N: WBG1.B38(OC1#/GPIO40) ; also on sheet 48
NOA_2_FM_USB_OC_2_N: R779.2 WBG1.A37(OC2#/GPIO41) ; also on sheet 48
NOA_3_FM_USB_OC_3_N: WBG1.B42(OC3#/GPIO42) ; also on sheet 48
NOA_5_FM_USB_OC_5_N: WBG1.G43(OC5#/GPIO9) ; also on sheet 48
NOA_6_FM_USB_OC_6_N: WBG1.L43(OC6#/GPIO10) ; also on sheet 48
NOA_7_FM_USB_OC_7_N: WBG1.J44(OC7#/GPIO14) ; also on sheet 48
P2E_WBG_BMC_RX_C_DN8: WBG1.AU10(PERN8) ; also on sheet 74
P2E_WBG_BMC_RX_C_DP8: WBG1.AU12(PERP8) ; also on sheet 74
P2E_WBG_BMC_TX_C_DN_8: C292.2 ; also on sheet 74
P2E_WBG_BMC_TX_C_DP_8: C291.2 ; also on sheet 74
P2E_WBG_BMC_TX_DN_8: C292.1 WBG1.AV2(PETN8)
P2E_WBG_BMC_TX_DP_8: C291.1 WBG1.AV4(PETP8)
P2E_WBG_LAN_RX_C_DN_5: WBG1.AP14(PERN5) ; also on sheet 64
P2E_WBG_LAN_RX_C_DP_5: WBG1.AP12(PERP5) ; also on sheet 64
P2E_WBG_LAN_TX_C_DN_5: C205.2 ; also on sheet 64
P2E_WBG_LAN_TX_C_DP_5: C204.2 ; also on sheet 64
P2E_WBG_LAN_TX_DN_5: C205.1 WBG1.AM4(PETN5)
P2E_WBG_LAN_TX_DP_5: C204.1 WBG1.AM2(PETP5)
P2E_WBG_NGFF_RX_C_DN_1: WBG1.AG6(PERN1/USB3RN3) ; also on sheet 83
P2E_WBG_NGFF_RX_C_DN_2: WBG1.AG14(PERN2/USB3RN4) ; also on sheet 83
P2E_WBG_NGFF_RX_C_DN_3: WBG1.AM12(PERN3) ; also on sheet 83
P2E_WBG_NGFF_RX_C_DN_4: WBG1.AM7(PERN4) ; also on sheet 83
P2E_WBG_NGFF_RX_C_DP_1: WBG1.AG7(PERP1/USB3RP3) ; also on sheet 83
P2E_WBG_NGFF_RX_C_DP_2: WBG1.AG15(PERP2/USB3RP4) ; also on sheet 83
P2E_WBG_NGFF_RX_C_DP_3: WBG1.AM10(PERP3) ; also on sheet 83
P2E_WBG_NGFF_RX_C_DP_4: WBG1.AM6(PERP4) ; also on sheet 83
P2E_WBG_NGFF_TX_C_DN_1: C280.2 ; also on sheet 83
P2E_WBG_NGFF_TX_C_DN_2: C285.2 ; also on sheet 83
P2E_WBG_NGFF_TX_C_DN_3: C287.2 ; also on sheet 83
P2E_WBG_NGFF_TX_C_DN_4: C289.2 ; also on sheet 83
P2E_WBG_NGFF_TX_C_DP_1: C284.2 ; also on sheet 83
P2E_WBG_NGFF_TX_C_DP_2: C286.2 ; also on sheet 83
P2E_WBG_NGFF_TX_C_DP_3: C288.2 ; also on sheet 83
P2E_WBG_NGFF_TX_C_DP_4: C290.2 ; also on sheet 83
P2E_WBG_NGFF_TX_DN_1: C280.1 WBG1.AD2(PETN1/USB3TN3)
P2E_WBG_NGFF_TX_DN_2: C285.1 WBG1.AF4(PETN2/USB3TN4)
P2E_WBG_NGFF_TX_DN_3: C287.1 WBG1.AH4(PETN3)
P2E_WBG_NGFF_TX_DN_4: C289.1 WBG1.AK4(PETN4)
P2E_WBG_NGFF_TX_DP_1: C284.1 WBG1.AD4(PETP1/USB3TP3)
P2E_WBG_NGFF_TX_DP_2: C286.1 WBG1.AF2(PETP2/USB3TP4)
P2E_WBG_NGFF_TX_DP_3: C288.1 WBG1.AH2(PETP3)
P2E_WBG_NGFF_TX_DP_4: C290.1 WBG1.AK2(PETP4)
P3E_CPU0_PE1_RISER1_RX_DN_0: PCIE1.A17 ; also on sheet 133
P3E_CPU0_PE1_RISER1_RX_DN_1: PCIE1.A22 ; also on sheet 133
P3E_CPU0_PE1_RISER1_RX_DN_2: PCIE1.A26 ; also on sheet 133
P3E_CPU0_PE1_RISER1_RX_DN_3: PCIE1.A30 ; also on sheet 133
P3E_CPU0_PE1_RISER1_RX_DN_4: PCIE1.A36 ; also on sheet 133
P3E_CPU0_PE1_RISER1_RX_DN_5: PCIE1.A40 ; also on sheet 133
P3E_CPU0_PE1_RISER1_RX_DN_6: PCIE1.A44 ; also on sheet 133
P3E_CPU0_PE1_RISER1_RX_DN_7: PCIE1.A48 ; also on sheet 133
P3E_CPU0_PE1_RISER1_RX_DP_0: PCIE1.A16 ; also on sheet 133
P3E_CPU0_PE1_RISER1_RX_DP_1: PCIE1.A21 ; also on sheet 133
P3E_CPU0_PE1_RISER1_RX_DP_2: PCIE1.A25 ; also on sheet 133
P3E_CPU0_PE1_RISER1_RX_DP_3: PCIE1.A29 ; also on sheet 133
P3E_CPU0_PE1_RISER1_RX_DP_4: PCIE1.A35 ; also on sheet 133
P3E_CPU0_PE1_RISER1_RX_DP_5: PCIE1.A39 ; also on sheet 133
P3E_CPU0_PE1_RISER1_RX_DP_6: PCIE1.A43 ; also on sheet 133
P3E_CPU0_PE1_RISER1_RX_DP_7: PCIE1.A47 ; also on sheet 133
P3E_CPU0_PE1_RISER1_TX_C_DN_0: PCIE1.B15 ; also on sheet 133
P3E_CPU0_PE1_RISER1_TX_C_DN_1: PCIE1.B20 ; also on sheet 133
P3E_CPU0_PE1_RISER1_TX_C_DN_2: PCIE1.B24 ; also on sheet 133
P3E_CPU0_PE1_RISER1_TX_C_DN_3: PCIE1.B28 ; also on sheet 133
P3E_CPU0_PE1_RISER1_TX_C_DN_4: PCIE1.B34 ; also on sheet 133
P3E_CPU0_PE1_RISER1_TX_C_DN_5: PCIE1.B38 ; also on sheet 133
P3E_CPU0_PE1_RISER1_TX_C_DN_6: PCIE1.B42 ; also on sheet 133
P3E_CPU0_PE1_RISER1_TX_C_DN_7: PCIE1.B46 ; also on sheet 133
P3E_CPU0_PE1_RISER1_TX_C_DP_0: PCIE1.B14 ; also on sheet 133
P3E_CPU0_PE1_RISER1_TX_C_DP_1: PCIE1.B19 ; also on sheet 133
P3E_CPU0_PE1_RISER1_TX_C_DP_2: PCIE1.B23 ; also on sheet 133
P3E_CPU0_PE1_RISER1_TX_C_DP_3: PCIE1.B27 ; also on sheet 133
P3E_CPU0_PE1_RISER1_TX_C_DP_4: PCIE1.B33 ; also on sheet 133
P3E_CPU0_PE1_RISER1_TX_C_DP_5: PCIE1.B37 ; also on sheet 133
P3E_CPU0_PE1_RISER1_TX_C_DP_6: PCIE1.B41 ; also on sheet 133
P3E_CPU0_PE1_RISER1_TX_C_DP_7: PCIE1.B45 ; also on sheet 133
P3E_CPU0_PE2_RISER1_RX_DN_0: PCIE1.A53 ; also on sheet 132
P3E_CPU0_PE2_RISER1_RX_DN_1: PCIE1.A57 ; also on sheet 132
P3E_CPU0_PE2_RISER1_RX_DN_2: PCIE1.A61 ; also on sheet 132
P3E_CPU0_PE2_RISER1_RX_DN_3: PCIE1.A65 ; also on sheet 132
P3E_CPU0_PE2_RISER1_RX_DN_4: PCIE1.A69 ; also on sheet 132
P3E_CPU0_PE2_RISER1_RX_DN_5: PCIE1.A73 ; also on sheet 132
P3E_CPU0_PE2_RISER1_RX_DN_6: PCIE1.A77 ; also on sheet 132
P3E_CPU0_PE2_RISER1_RX_DN_7: PCIE1.A81 ; also on sheet 132
P3E_CPU0_PE2_RISER1_RX_DN_8: PCIE1.A86 ; also on sheet 132
P3E_CPU0_PE2_RISER1_RX_DN_9: PCIE1.A90 ; also on sheet 132
P3E_CPU0_PE2_RISER1_RX_DN_10: PCIE1.A94 ; also on sheet 132
P3E_CPU0_PE2_RISER1_RX_DN_11: PCIE1.A98 ; also on sheet 132
P3E_CPU0_PE2_RISER1_RX_DN_12: PCIE1.A102 ; also on sheet 132
P3E_CPU0_PE2_RISER1_RX_DN_13: PCIE1.A106 ; also on sheet 132
P3E_CPU0_PE2_RISER1_RX_DN_14: PCIE1.A110 ; also on sheet 132
P3E_CPU0_PE2_RISER1_RX_DN_15: PCIE1.A114 ; also on sheet 132
P3E_CPU0_PE2_RISER1_RX_DP_0: PCIE1.A52 ; also on sheet 132
P3E_CPU0_PE2_RISER1_RX_DP_1: PCIE1.A56 ; also on sheet 132
P3E_CPU0_PE2_RISER1_RX_DP_2: PCIE1.A60 ; also on sheet 132
P3E_CPU0_PE2_RISER1_RX_DP_3: PCIE1.A64 ; also on sheet 132
P3E_CPU0_PE2_RISER1_RX_DP_4: PCIE1.A68 ; also on sheet 132
P3E_CPU0_PE2_RISER1_RX_DP_5: PCIE1.A72 ; also on sheet 132
P3E_CPU0_PE2_RISER1_RX_DP_6: PCIE1.A76 ; also on sheet 132
P3E_CPU0_PE2_RISER1_RX_DP_7: PCIE1.A80 ; also on sheet 132
P3E_CPU0_PE2_RISER1_RX_DP_8: PCIE1.A85 ; also on sheet 132
P3E_CPU0_PE2_RISER1_RX_DP_9: PCIE1.A89 ; also on sheet 132
P3E_CPU0_PE2_RISER1_RX_DP_10: PCIE1.A93 ; also on sheet 132
P3E_CPU0_PE2_RISER1_RX_DP_11: PCIE1.A97 ; also on sheet 132
P3E_CPU0_PE2_RISER1_RX_DP_12: PCIE1.A101 ; also on sheet 132
P3E_CPU0_PE2_RISER1_RX_DP_13: PCIE1.A105 ; also on sheet 132
P3E_CPU0_PE2_RISER1_RX_DP_14: PCIE1.A109 ; also on sheet 132
P3E_CPU0_PE2_RISER1_RX_DP_15: PCIE1.A113 ; also on sheet 132
P3E_CPU0_PE2_RISER1_TX_C_DN_0: C147.1 PCIE1.B51
P3E_CPU0_PE2_RISER1_TX_C_DN_1: C144.1 PCIE1.B55
P3E_CPU0_PE2_RISER1_TX_C_DN_2: C141.1 PCIE1.B59
P3E_CPU0_PE2_RISER1_TX_C_DN_3: C138.1 PCIE1.B63
P3E_CPU0_PE2_RISER1_TX_C_DN_4: C135.1 PCIE1.B67
P3E_CPU0_PE2_RISER1_TX_C_DN_5: C132.1 PCIE1.B71
P3E_CPU0_PE2_RISER1_TX_C_DN_6: C129.1 PCIE1.B75
P3E_CPU0_PE2_RISER1_TX_C_DN_7: C126.1 PCIE1.B79
P3E_CPU0_PE2_RISER1_TX_C_DN_8: C123.1 PCIE1.B84
P3E_CPU0_PE2_RISER1_TX_C_DN_9: C120.1 PCIE1.B88
P3E_CPU0_PE2_RISER1_TX_C_DN_10: C117.1 PCIE1.B92
P3E_CPU0_PE2_RISER1_TX_C_DN_11: C114.1 PCIE1.B96
P3E_CPU0_PE2_RISER1_TX_C_DN_12: C111.1 PCIE1.B100
P3E_CPU0_PE2_RISER1_TX_C_DN_13: C108.1 PCIE1.B104
P3E_CPU0_PE2_RISER1_TX_C_DN_14: C105.1 PCIE1.B108
P3E_CPU0_PE2_RISER1_TX_C_DN_15: C102.1 PCIE1.B112
P3E_CPU0_PE2_RISER1_TX_C_DP_0: C146.1 PCIE1.B50
P3E_CPU0_PE2_RISER1_TX_C_DP_1: C143.1 PCIE1.B54
P3E_CPU0_PE2_RISER1_TX_C_DP_2: C140.1 PCIE1.B58
P3E_CPU0_PE2_RISER1_TX_C_DP_3: C137.1 PCIE1.B62
P3E_CPU0_PE2_RISER1_TX_C_DP_4: C134.1 PCIE1.B66
P3E_CPU0_PE2_RISER1_TX_C_DP_5: C131.1 PCIE1.B70
P3E_CPU0_PE2_RISER1_TX_C_DP_6: C128.1 PCIE1.B74
P3E_CPU0_PE2_RISER1_TX_C_DP_7: C125.1 PCIE1.B78
P3E_CPU0_PE2_RISER1_TX_C_DP_8: C122.1 PCIE1.B83
P3E_CPU0_PE2_RISER1_TX_C_DP_9: C119.1 PCIE1.B87
P3E_CPU0_PE2_RISER1_TX_C_DP_10: C116.1 PCIE1.B91
P3E_CPU0_PE2_RISER1_TX_C_DP_11: C113.1 PCIE1.B95
P3E_CPU0_PE2_RISER1_TX_C_DP_12: C110.1 PCIE1.B99
P3E_CPU0_PE2_RISER1_TX_C_DP_13: C107.1 PCIE1.B103
P3E_CPU0_PE2_RISER1_TX_C_DP_14: C104.1 PCIE1.B107
P3E_CPU0_PE2_RISER1_TX_C_DP_15: C101.1 PCIE1.B111
P3E_CPU0_PE2_RISER1_TX_DN_0: C147.2 ; also on sheet 132
P3E_CPU0_PE2_RISER1_TX_DN_1: C144.2 ; also on sheet 132
P3E_CPU0_PE2_RISER1_TX_DN_2: C141.2 ; also on sheet 132
P3E_CPU0_PE2_RISER1_TX_DN_3: C138.2 ; also on sheet 132
P3E_CPU0_PE2_RISER1_TX_DN_4: C135.2 ; also on sheet 132
P3E_CPU0_PE2_RISER1_TX_DN_5: C132.2 ; also on sheet 132
P3E_CPU0_PE2_RISER1_TX_DN_6: C129.2 ; also on sheet 132
P3E_CPU0_PE2_RISER1_TX_DN_7: C126.2 ; also on sheet 132
P3E_CPU0_PE2_RISER1_TX_DN_8: C123.2 ; also on sheet 132
P3E_CPU0_PE2_RISER1_TX_DN_9: C120.2 ; also on sheet 132
P3E_CPU0_PE2_RISER1_TX_DN_10: C117.2 ; also on sheet 132
P3E_CPU0_PE2_RISER1_TX_DN_11: C114.2 ; also on sheet 132
P3E_CPU0_PE2_RISER1_TX_DN_12: C111.2 ; also on sheet 132
P3E_CPU0_PE2_RISER1_TX_DN_13: C108.2 ; also on sheet 132
P3E_CPU0_PE2_RISER1_TX_DN_14: C105.2 ; also on sheet 132
P3E_CPU0_PE2_RISER1_TX_DN_15: C102.2 ; also on sheet 132
P3E_CPU0_PE2_RISER1_TX_DP_0: C146.2 ; also on sheet 132
P3E_CPU0_PE2_RISER1_TX_DP_1: C143.2 ; also on sheet 132
P3E_CPU0_PE2_RISER1_TX_DP_2: C140.2 ; also on sheet 132
P3E_CPU0_PE2_RISER1_TX_DP_3: C137.2 ; also on sheet 132
P3E_CPU0_PE2_RISER1_TX_DP_4: C134.2 ; also on sheet 132
P3E_CPU0_PE2_RISER1_TX_DP_5: C131.2 ; also on sheet 132
P3E_CPU0_PE2_RISER1_TX_DP_6: C128.2 ; also on sheet 132
P3E_CPU0_PE2_RISER1_TX_DP_7: C125.2 ; also on sheet 132
P3E_CPU0_PE2_RISER1_TX_DP_8: C122.2 ; also on sheet 132
P3E_CPU0_PE2_RISER1_TX_DP_9: C119.2 ; also on sheet 132
P3E_CPU0_PE2_RISER1_TX_DP_10: C116.2 ; also on sheet 132
P3E_CPU0_PE2_RISER1_TX_DP_11: C113.2 ; also on sheet 132
P3E_CPU0_PE2_RISER1_TX_DP_12: C110.2 ; also on sheet 132
P3E_CPU0_PE2_RISER1_TX_DP_13: C107.2 ; also on sheet 132
P3E_CPU0_PE2_RISER1_TX_DP_14: C104.2 ; also on sheet 132
P3E_CPU0_PE2_RISER1_TX_DP_15: C101.2 ; also on sheet 132
P3E_CPU0_PE3_MEZZ_RX_DN_8: MEZCN1.31 ; also on sheet 131
P3E_CPU0_PE3_MEZZ_RX_DN_9: MEZCN1.35 ; also on sheet 131
P3E_CPU0_PE3_MEZZ_RX_DN_10: MEZCN1.39 ; also on sheet 131
P3E_CPU0_PE3_MEZZ_RX_DN_11: MEZCN1.43 ; also on sheet 131
P3E_CPU0_PE3_MEZZ_RX_DN_12: MEZCN1.47 ; also on sheet 131
P3E_CPU0_PE3_MEZZ_RX_DN_13: MEZCN1.51 ; also on sheet 131
P3E_CPU0_PE3_MEZZ_RX_DN_14: MEZCN1.55 ; also on sheet 131
P3E_CPU0_PE3_MEZZ_RX_DN_15: MEZCN1.59 ; also on sheet 131
P3E_CPU0_PE3_MEZZ_RX_DP_8: MEZCN1.30 ; also on sheet 131
P3E_CPU0_PE3_MEZZ_RX_DP_9: MEZCN1.34 ; also on sheet 131
P3E_CPU0_PE3_MEZZ_RX_DP_10: MEZCN1.38 ; also on sheet 131
P3E_CPU0_PE3_MEZZ_RX_DP_11: MEZCN1.42 ; also on sheet 131
P3E_CPU0_PE3_MEZZ_RX_DP_12: MEZCN1.46 ; also on sheet 131
P3E_CPU0_PE3_MEZZ_RX_DP_13: MEZCN1.50 ; also on sheet 131
P3E_CPU0_PE3_MEZZ_RX_DP_14: MEZCN1.54 ; also on sheet 131
P3E_CPU0_PE3_MEZZ_RX_DP_15: MEZCN1.58 ; also on sheet 131
P3E_CPU0_PE3_MEZZ_TX_C_DN_8: C59.2 MEZCN1.89
P3E_CPU0_PE3_MEZZ_TX_C_DN_9: C62.2 MEZCN1.93
P3E_CPU0_PE3_MEZZ_TX_C_DN_10: C71.2 MEZCN1.97
P3E_CPU0_PE3_MEZZ_TX_C_DN_11: C80.2 MEZCN1.101
P3E_CPU0_PE3_MEZZ_TX_C_DN_12: C86.2 MEZCN1.105
P3E_CPU0_PE3_MEZZ_TX_C_DN_13: C92.2 MEZCN1.109
P3E_CPU0_PE3_MEZZ_TX_C_DN_14: C98.2 MEZCN1.113
P3E_CPU0_PE3_MEZZ_TX_C_DN_15: C99.2 MEZCN1.117
P3E_CPU0_PE3_MEZZ_TX_C_DP_8: C56.2 MEZCN1.88
P3E_CPU0_PE3_MEZZ_TX_C_DP_9: C65.2 MEZCN1.92
P3E_CPU0_PE3_MEZZ_TX_C_DP_10: C68.2 MEZCN1.96
P3E_CPU0_PE3_MEZZ_TX_C_DP_11: C74.2 MEZCN1.100
P3E_CPU0_PE3_MEZZ_TX_C_DP_12: C83.2 MEZCN1.104
P3E_CPU0_PE3_MEZZ_TX_C_DP_13: C89.2 MEZCN1.108
P3E_CPU0_PE3_MEZZ_TX_C_DP_14: C95.2 MEZCN1.112
P3E_CPU0_PE3_MEZZ_TX_C_DP_15: C100.2 MEZCN1.116
P3E_CPU0_PE3_MEZZ_TX_DN_8: C59.1 ; also on sheet 131
P3E_CPU0_PE3_MEZZ_TX_DN_9: C62.1 ; also on sheet 131
P3E_CPU0_PE3_MEZZ_TX_DN_10: C71.1 ; also on sheet 131
P3E_CPU0_PE3_MEZZ_TX_DN_11: C80.1 ; also on sheet 131
P3E_CPU0_PE3_MEZZ_TX_DN_12: C86.1 ; also on sheet 131
P3E_CPU0_PE3_MEZZ_TX_DN_13: C92.1 ; also on sheet 131
P3E_CPU0_PE3_MEZZ_TX_DN_14: C98.1 ; also on sheet 131
P3E_CPU0_PE3_MEZZ_TX_DN_15: C99.1 ; also on sheet 131
P3E_CPU0_PE3_MEZZ_TX_DP_8: C56.1 ; also on sheet 131
P3E_CPU0_PE3_MEZZ_TX_DP_9: C65.1 ; also on sheet 131
P3E_CPU0_PE3_MEZZ_TX_DP_10: C68.1 ; also on sheet 131
P3E_CPU0_PE3_MEZZ_TX_DP_11: C74.1 ; also on sheet 131
P3E_CPU0_PE3_MEZZ_TX_DP_12: C83.1 ; also on sheet 131
P3E_CPU0_PE3_MEZZ_TX_DP_13: C89.1 ; also on sheet 131
P3E_CPU0_PE3_MEZZ_TX_DP_14: C95.1 ; also on sheet 131
P3E_CPU0_PE3_MEZZ_TX_DP_15: C100.1 ; also on sheet 131
P3E_CPU0_PE3_RISER2_RX_DN_0: MIDCN2.B1(PCIE_RX_DN0) ; also on sheet 131
P3E_CPU0_PE3_RISER2_RX_DN_1: MIDCN2.E1(PCIE_RX_DN1) ; also on sheet 131
P3E_CPU0_PE3_RISER2_RX_DN_2: MIDCN2.H1(PCIE_RX_DN2) ; also on sheet 131
P3E_CPU0_PE3_RISER2_RX_DN_3: MIDCN2.C2(PCIE_RX_DN3) ; also on sheet 131
P3E_CPU0_PE3_RISER2_RX_DN_4: MIDCN2.F2(PCIE_RX_DN4) ; also on sheet 131
P3E_CPU0_PE3_RISER2_RX_DN_5: MIDCN2.I2(PCIE_RX_DN5) ; also on sheet 131
P3E_CPU0_PE3_RISER2_RX_DN_6: MIDCN2.B3(PCIE_RX_DN6) ; also on sheet 131
P3E_CPU0_PE3_RISER2_RX_DN_7: MIDCN2.E3(PCIE_RX_DN7) ; also on sheet 131
P3E_CPU0_PE3_RISER2_RX_DP_0: MIDCN2.A1(PCIE_RX_DP0) ; also on sheet 131
P3E_CPU0_PE3_RISER2_RX_DP_1: MIDCN2.D1(PCIE_RX_DP1) ; also on sheet 131
P3E_CPU0_PE3_RISER2_RX_DP_2: MIDCN2.G1(PCIE_RX_DP2) ; also on sheet 131
P3E_CPU0_PE3_RISER2_RX_DP_3: MIDCN2.B2(PCIE_RX_DP3) ; also on sheet 131
P3E_CPU0_PE3_RISER2_RX_DP_4: MIDCN2.E2(PCIE_RX_DP4) ; also on sheet 131
P3E_CPU0_PE3_RISER2_RX_DP_5: MIDCN2.H2(PCIE_RX_DP5) ; also on sheet 131
P3E_CPU0_PE3_RISER2_RX_DP_6: MIDCN2.A3(PCIE_RX_DP6) ; also on sheet 131
P3E_CPU0_PE3_RISER2_RX_DP_7: MIDCN2.D3(PCIE_RX_DP7) ; also on sheet 131
P3E_CPU0_PE3_RISER2_TX_C_DN_0: C195.1 MIDCN2.C8(PCIE_TX_DN0)
P3E_CPU0_PE3_RISER2_TX_C_DN_1: C192.1 MIDCN2.F8(PCIE_TX_DN1)
P3E_CPU0_PE3_RISER2_TX_C_DN_2: C189.1 MIDCN2.I8(PCIE_TX_DN2)
P3E_CPU0_PE3_RISER2_TX_C_DN_3: C186.1 MIDCN2.B7(PCIE_TX_DN3)
P3E_CPU0_PE3_RISER2_TX_C_DN_4: C183.1 MIDCN2.E7(PCIE_TX_DN4)
P3E_CPU0_PE3_RISER2_TX_C_DN_5: C180.1 MIDCN2.H7(PCIE_TX_DN5)
P3E_CPU0_PE3_RISER2_TX_C_DN_6: C177.1 MIDCN2.F6(PCIE_TX_DN6)
P3E_CPU0_PE3_RISER2_TX_C_DN_7: C174.1 MIDCN2.I6(PCIE_TX_DN7)
P3E_CPU0_PE3_RISER2_TX_C_DP_0: C194.1 MIDCN2.B8(PCIE_TX_DP0)
P3E_CPU0_PE3_RISER2_TX_C_DP_1: C191.1 MIDCN2.E8(PCIE_TX_DP1)
P3E_CPU0_PE3_RISER2_TX_C_DP_2: C188.1 MIDCN2.H8(PCIE_TX_DP2)
P3E_CPU0_PE3_RISER2_TX_C_DP_3: C185.1 MIDCN2.A7(PCIE_TX_DP3)
P3E_CPU0_PE3_RISER2_TX_C_DP_4: C182.1 MIDCN2.D7(PCIE_TX_DP4)
P3E_CPU0_PE3_RISER2_TX_C_DP_5: C179.1 MIDCN2.G7(PCIE_TX_DP5)
P3E_CPU0_PE3_RISER2_TX_C_DP_6: C176.1 MIDCN2.E6(PCIE_TX_DP6)
P3E_CPU0_PE3_RISER2_TX_C_DP_7: C173.1 MIDCN2.H6(PCIE_TX_DP7)
P3E_CPU0_PE3_RISER2_TX_DN_0: C195.2 ; also on sheet 131
P3E_CPU0_PE3_RISER2_TX_DN_1: C192.2 ; also on sheet 131
P3E_CPU0_PE3_RISER2_TX_DN_2: C189.2 ; also on sheet 131
P3E_CPU0_PE3_RISER2_TX_DN_3: C186.2 ; also on sheet 131
P3E_CPU0_PE3_RISER2_TX_DN_4: C183.2 ; also on sheet 131
P3E_CPU0_PE3_RISER2_TX_DN_5: C180.2 ; also on sheet 131
P3E_CPU0_PE3_RISER2_TX_DN_6: C177.2 ; also on sheet 131
P3E_CPU0_PE3_RISER2_TX_DN_7: C174.2 ; also on sheet 131
P3E_CPU0_PE3_RISER2_TX_DP_0: C194.2 ; also on sheet 131
P3E_CPU0_PE3_RISER2_TX_DP_1: C191.2 ; also on sheet 131
P3E_CPU0_PE3_RISER2_TX_DP_2: C188.2 ; also on sheet 131
P3E_CPU0_PE3_RISER2_TX_DP_3: C185.2 ; also on sheet 131
P3E_CPU0_PE3_RISER2_TX_DP_4: C182.2 ; also on sheet 131
P3E_CPU0_PE3_RISER2_TX_DP_5: C179.2 ; also on sheet 131
P3E_CPU0_PE3_RISER2_TX_DP_6: C176.2 ; also on sheet 131
P3E_CPU0_PE3_RISER2_TX_DP_7: C173.2 ; also on sheet 131
PCIE_SLOT0_CONFIG: PCIE1.A50 R518.2 ; also on sheet 166
PCIE_SLOT1_CONFIG: PCIE1.A83 R520.2 ; also on sheet 166
PCIE_SLOT_CPRSNT1_N: PCIE1.B17 R1645.2
PCIE_SLOT_CPRSNT2_N: PCIE1.B31 R1646.2
PCIE_SLOT_CPRSNT3_N: PCIE1.B48 R1650.2
PCIE_SLOT_CPRSNT4_N: PCIE1.B81 R1651.2
PCIE_SLOT_CPRSNT5_N: PCIE1.B114 R1652.2
PCIE_SLOT_CPRSNT6_N: PCIE1.B115 R1653.2
PD_SLOT1_PRSNT1_N: PCIE1.A1 R701.1
POWER_FAIL_N: MIDCN1.3 ; also on sheet 48 52 54 61 177
PS_REDUNDANT_LOST_N: MIDCN1.2 ; also on sheet 177
RMII_NCSI_BMC_CRS_DV: MEZCN1.14 ; also on sheet 180
RMII_NCSI_BMC_PHY_TXD0: MEZCN1.80 ; also on sheet 180
RMII_NCSI_BMC_PHY_TXD1: MEZCN1.81 ; also on sheet 180
RMII_NCSI_BMC_RX_ER: MEZCN1.78 ; also on sheet 180
RMII_NCSI_BMC_TX_EN: MEZCN1.16 ; also on sheet 180
RMII_NCSI_PHY_BMC_RXD0: MEZCN1.22 ; also on sheet 180
RMII_NCSI_PHY_BMC_RXD1: MEZCN1.23 ; also on sheet 180
RST_PERST0_N: MEZCN1.17 PCIE1.A11 R1053.2 ; also on sheet 51 168
RST_PERST0_N_MID: MIDCN2.I5(PCIE_PERST#) R1053.1
SMB6_RISER2_CLK_R: MEZCN1.18 R1522.2
SMB6_RISER2_DAT_R: MEZCN1.19 R1523.2
SMB_BMC_MEZZ_SCL: R1522.1 ; also on sheet 74
SMB_BMC_MEZZ_SDA: R1523.1 ; also on sheet 74
SMB_MAIN_CLK: R480.1 ; also on sheet 74
SMB_MAIN_DATA: R482.1 ; also on sheet 74
SMB_PMBUS_CLK: MIDCN1.7 MIDCN2.C6(PMBUS_CLK) ; also on sheet 162
SMB_PMBUS_DATA: MIDCN1.6 MIDCN2.B6(PMBUS_DATA) ; also on sheet 162
TP_PCH_RSVD_2: R889.1 WBG1.V12(RESERVED#V12)
TP_PCH_RSVD_3: R888.1 WBG1.V10(RESERVED#V10)
USB2_00_DN: WBG1.AV48(USB2N0) ; also on sheet 177
USB2_00_DP: WBG1.AV46(USB2P0) ; also on sheet 177
USB2_01_DN: WBG1.AY48(USB2N1) ; also on sheet 176
USB2_01_DP: WBG1.AY46(USB2P1) ; also on sheet 176
USB2_02_DN: WBG1.AJ36(USB2N2) ; also on sheet 176
USB2_02_DP: WBG1.AJ35(USB2P2) ; also on sheet 176
USB3_01_RXN: WBG1.AA7(USB3RN1) ; also on sheet 176
USB3_01_RXP: WBG1.AA6(USB3RP1) ; also on sheet 176
USB3_01_TXN: WBG1.T2(USB3TN1) ; also on sheet 176
USB3_01_TXP: WBG1.T4(USB3TP1) ; also on sheet 176
USB3_02_RXN: WBG1.AA14(USB3RN2) ; also on sheet 176
USB3_02_RXP: WBG1.AA15(USB3RP2) ; also on sheet 176
USB3_02_TXN: WBG1.V2(USB3TN2) ; also on sheet 176
USB3_02_TXP: WBG1.V4(USB3TP2) ; also on sheet 176

Not connected (* = marked no-connect by the designer): MEZCN1 NP1* NP2*; PCIE1 NP1* NP2*; WBG1 AB2(USB3TN6)* AB4(USB3TP6)* AC7(USB3RN6)* AC9(USB3RP6)* AC12(USB3RP5)* AC14(USB3RN5)* AC36(USB2N13)* AC38(USB2P13)* AC40(USB2N11)* AC41(USB2P11)* AC43(USB2P12)* AC44(USB2N12)* AG35(USB2P10)* AG36(USB2N10)* AG40(USB2N9)* AG41(USB2P9)* AG43(USB2N8)* AG44(USB2P8)* AJ40(USB2N5)* AJ41(USB2P5)* AJ43(USB2P6)* AJ44(USB2N6)* AM40(USB2P4)* AM41(USB2N4)* AM43(USB2P7)* AM44(USB2N7)* AP2(PETP6)* AP4(PETN6)* AP7(PERP6)* AP9(PERN6)* AP43(USB2P3)* AP44(USB2N3)* AT2(PETP7)* AT4(PETN7)* AU6(PERN7)* AU7(PERP7)* Y2(USB3TN5)* Y4(USB3TP5)*

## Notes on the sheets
sheet 92
- WELLSBURG - DMI & USB
- FROM WBG iCLK
- TO BMC
- FAB1 20150309
- Place close to CPU0
- 0.1U 16V K0402 X7R
- 0.1U 16V K0402 X7R
- Please place clost to NGFF0.
- Note :
- No external resistors are required.
  Ensure appropriate ESD and EMI suppression devices are in place.
  These signals have integrated 15 k pull-down resistors. Unused
  USB ports can be left as no connect.
- 1.Sharing of OC pins is required to cover all 14 USB
- connectors but no more than 1 OC line may be connected
- to a USB connector.
- 2.OC[3:0]# should be connected with USB2.0 ports 0-7.
- 3.OC[7:4]# should be connected with USB2.0 ports 8-13.
- TO Front USB
- TO Vertical USB
- USB MAPPING
- USB2 PORT
- USB3 PORT
- OC
- LOCATION
- BMC
- 0
- NA
- 0
- 1
- 1
- 0
- INT. USB
- 2
- 2
- 1
- EXT. USB
- These signals are not used when the PCH is in
  Native isCLK or PCH Hybrid Mode and must be
  terminated properly using one (for REF14 input)
  or two (for differential inputs) separate 10kohm
  pulldown resistors. This is for reliability concerns
  during platform power-on.
- 3
- NOT USED
- NA
- NOT USED
- 4
- NOT USED
- NA
- NOT USED
- 5
- NOT USED
- NA
- NOT USED
- 6
- NOT USED
- NA
- NOT USED
- 7
- NA
- NA
- NOT USED
- 8
- NA
- NA
- NOT USED
- 9
- NA
- NA
- NOT USED
- 10
- NA
- NA
- NOT USED
- 11
- NA
- NA
- NOT USED
- 12
- NA
- NA
- NOT USED
- 13
- NA
- NA
- NOT USED
sheet 93
- MID-PLANE CONNECTOR
- FAB1 REV006 20150324
- FAB1 REV010 20150331
- FAB1 REV008 20150326
- FAB1 REV014 20150416
- Change to 84.27002.N31
- FAB1 REV005 20150323
- Vf = 0.47V
- FAB1 REV013 20150414
sheet 94
- PCIE RISER
- FAB1 REV001 20150316
- Delete components
- FROM DB1900Z
- CHIP CAP C 0.1U 25V J0603 X7R
- FAB1 20150126
sheet 95
- MEZZ CONNECTOR
- FAB1 REV004 20150320
- CHIP CAP C 0.22U 16V K0402 X7R
- CAD NOTE:
  PLACE ALL CAPS NEAR TO MEZZ1
